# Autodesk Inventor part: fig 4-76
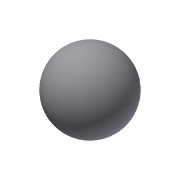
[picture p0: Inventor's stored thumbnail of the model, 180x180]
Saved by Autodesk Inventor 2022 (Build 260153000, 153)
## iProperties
Created: 2012-07
Part Number: fig 4-76
Material: Generic
Document SubType Name: Modeling
Designer: CADCIM
Density: 1 g/cm^3
Appearance: Default
Author: CADCIM
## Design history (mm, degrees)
sketch "Sketch1"
  geometry: L1 (7.807, -5.174)-(-7.807, 5.174); A1 r 9.366 centre (0, 0) between (7.807, -5.174) and (-7.807, 5.174)
  constraints: 2 end point, 2 point on circle, 1 centre point, 1 midpoint
  dimensions: "d0" = 90 deg dimension on A1.centre A1 L1.start L1.end L1
revolve "Revolution1" sketch "Sketch1" stored, may be unused: angle "d0" = 90 deg
body "Solid1"
